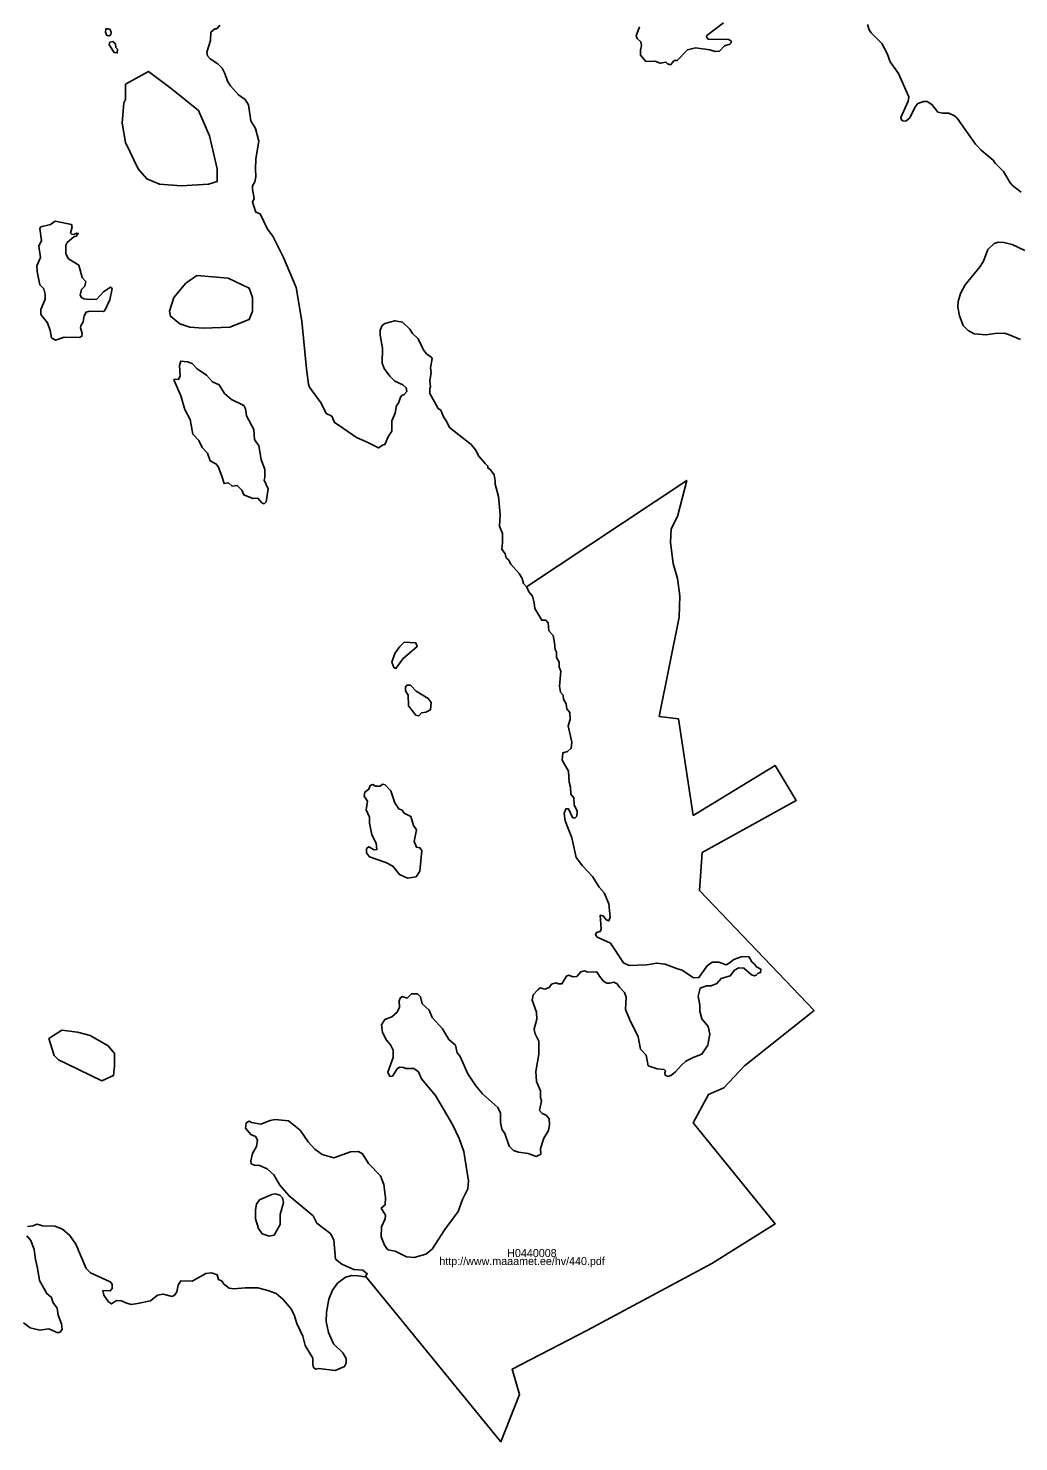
# Model space of a CAD drawing. Extents: x 369010 to 739155, y 6377141 to 6634081.
# Drawn here: x 378617 to 381710, y 6464683 to 6469097 of the extents above; entities that cross this region are included whole.
import ezdxf

# ---------------------------------------------------------------- set-up
doc = ezdxf.new("R2010")
doc.units = 0
for name, color, linetype in [('H_LINK', 7, 'Continuous'), ('H_PIIR', 7, 'Continuous'), ('H_TUNNUS', 7, 'Continuous')]:
    doc.layers.add(name, color=color, linetype=linetype)

msp = doc.modelspace()

# ---------------------------------------------------------------- linework, layer by layer
at = {"layer": 'H_PIIR'}
for points in [[(380525.63, 6469101.3447), (380515.3699, 6469073.5447), (380519.01, 6469065.6047), (380529.9301, 6469055.0147), (380531.92, 6469043.1047), (380528.94, 6469028.5447), (380529.2701, 6469013.3146), (380545.81, 6468993.4647), (380573.28, 6468994.4547), (380590.4901, 6468988.1647), (380608.3601, 6468991.4746), (380613.32, 6468986.5147), (380622.5899, 6468983.5347), (380634.1699, 6468996.1146), (380643.4299, 6468997.1046), (380675.1999, 6469029.5346), (380701.01, 6469035.8246), (380745.36, 6469029.5346), (380762.56, 6469024.9046), (380775.1401, 6469026.2247), (380791.02, 6469042.4347), (380808.23, 6469047.7347), (380811.8699, 6469051.7047), (380811.8699, 6469057.3247), (380804.9199, 6469061.9647), (380740.72, 6469062.9546), (380735.43, 6469070.8946), (380735.7599, 6469074.5346), (380788.04, 6469114.5747)], [(381237.7499, 6469109.2847), (381243.0501, 6469092.0747), (381248.6799, 6469083.4747), (381282.7599, 6469050.0447), (381299.3, 6469018.6146), (381308.2401, 6468992.8047), (381334.0499, 6468956.4047), (381366.4801, 6468883.6046), (381364.49, 6468869.7046), (381341.99, 6468818.0747), (381343.9801, 6468811.1247), (381347.9499, 6468808.4846), (381357.2201, 6468807.1546), (381369.46, 6468817.7446), (381386.6701, 6468851.8346), (381395.2699, 6468862.7546), (381412.4799, 6468868.3746), (381424.39, 6468868.0446), (381438.95, 6468859.4447), (381457.81, 6468834.9546), (381473.36, 6468832.3047), (381491.24, 6468832.6346), (381509.1, 6468823.7047), (381517.7101, 6468816.0946), (381574.6199, 6468735.3547), (381592.82, 6468716.8246), (381629.89, 6468685.0546), (381636.5101, 6468675.7846), (381662.3199, 6468650.3046), (381683.1599, 6468614.8947), (381690.44, 6468606.2947), (381717.9101, 6468585.1146)], [(378614.47, 6465354.6846), (378631.1, 6465357.0646), (378645.3599, 6465362.2946), (378661.99, 6465357.0646), (378700.01, 6465355.6447), (378724.25, 6465346.6046), (378747.0601, 6465326.6447), (378765.6, 6465299.5547), (378797.91, 6465223.5047), (378811.69, 6465210.1947), (378873, 6465182.1546), (378879.1801, 6465174.5546), (378879.1801, 6465161.7147), (378873.47, 6465153.6347), (378850.1899, 6465155.0646), (378853.51, 6465140.3247), (378867.3, 6465119.4147), (378876.8001, 6465113.2347), (378892.48, 6465124.1647), (378908.16, 6465123.2146), (378921.47, 6465116.0847), (378939.0499, 6465111.8146), (378958.0599, 6465114.1946), (378999.4, 6465122.7546), (379021.26, 6465140.8147), (379038.3701, 6465143.6647), (379066.89, 6465136.5346), (379074.97, 6465141.2846), (379081.6201, 6465150.7947), (379084.9499, 6465172.1846), (379093.5, 6465185.4946), (379129.14, 6465184.5446), (379171.91, 6465208.3047), (379189.0201, 6465210.6847), (379206.61, 6465204.0346), (379210.8801, 6465189.7746), (379222.2899, 6465184.5446), (379225.62, 6465177.4146), (379244.15, 6465162.2047), (379258.88, 6465160.7746), (379294.5201, 6465163.6246), (379334.2099, 6465163.6346), (379365.5701, 6465155.5546), (379391.23, 6465145.5747), (379413.09, 6465126.5647), (379436.86, 6465098.5146), (379447.3099, 6465079.5046), (379456.34, 6465051.9347), (379474.3999, 6465012.9646), (379482.24, 6464983.4947), (379505.52, 6464944.0447), (379505.52, 6464924.0846), (379507.4201, 6464914.5746), (379515.5001, 6464909.3446), (379525.01, 6464911.2547), (379575.86, 6464905.5447), (379604.8499, 6464917.9046), (379610.0699, 6464928.3646), (379610.31, 6464943.0947), (379599.86, 6464960.6746), (379570.3901, 6464988.7246), (379554.7099, 6465023.4146), (379547.1099, 6465058.5946), (379548.2999, 6465087.5846), (379555.9001, 6465128.4646), (379566.8299, 6465156.5047), (379582.9901, 6465178.3747), (379607.6999, 6465196.9047), (379627.66, 6465202.1347), (379647.1501, 6465201.1846), (379668.06, 6465197.8546), (379670.0236, 6465200.3116), (380092.86, 6464682.77), (380151.61, 6464830.17), (380128.11, 6464909.2199), (380363.1101, 6465030.9899), (380751.73, 6465239.08), (380949.3601, 6465363.18), (380693.51, 6465679.2), (380741.15, 6465766.9), (380788.7899, 6465788.41), (380854.0801, 6465856.2501), (381071.1101, 6466029.98), (380712.92, 6466403.93), (380721.74, 6466523.0599), (381014.65, 6466685.2199), (380949.3601, 6466794.4201), (380693.51, 6466638.87), (380647.6301, 6466940.03), (380587.64, 6466948.2999), (380649.39, 6467257.7201), (380651.91, 6467324.6501), (380644.1601, 6467378.95), (380630.59, 6467425.4999), (380622.84, 6467491.4301), (380624.77, 6467534.1001), (380644.1601, 6467572.89), (380673.24, 6467685.37), (380172.6387, 6467352.8072), (380163.9299, 6467363.3247), (380159.18, 6467378.5347), (380149.92, 6467394.6947), (380123.78, 6467423.6946), (380117.13, 6467436.9946), (380109.05, 6467443.6547), (380106.1999, 6467456.0146), (380095.74, 6467470.7447), (380098.1199, 6467491.1846), (380098.1199, 6467519.2247), (380088.85, 6467542.0446), (380090.28, 6467579.1147), (380085.9999, 6467635.2047), (380075.58, 6467673.3347), (380075.58, 6467684.0346), (380071.94, 6467702.9046), (380060.6899, 6467717.7947), (380052.42, 6467724.0747), (380052.42, 6467729.7047), (380043.4901, 6467737.6446), (380024.2899, 6467761.1446), (380013.3699, 6467780.3346), (380000.1399, 6467797.2047), (379932.3, 6467850.1546), (379924.69, 6467868.3547), (379914.0999, 6467883.5746), (379905.16, 6467904.0947), (379896.8901, 6467909.7247), (379870.75, 6467956.3746), (379871.08, 6467973.5846), (379873.4, 6467977.2247), (379871.4099, 6467997.4147), (379875.71, 6468021.2347), (379872.7401, 6468037.1246), (379878.03, 6468065.5847), (379875.38, 6468070.5446), (379860.82, 6468080.8046), (379849.9, 6468093.7046), (379846.5899, 6468104.6246), (379834.0201, 6468128.4547), (379817.47, 6468144.0047), (379808.21, 6468157.9047), (379785.7, 6468179.0846), (379761.8801, 6468183.7146), (379730.1099, 6468175.4446), (379722.4999, 6468169.4847), (379715.88, 6468154.2646), (379716.2099, 6468138.3847), (379723.1599, 6468098.6746), (379722.17, 6468051.0246), (379728.13, 6468035.1347), (379746.66, 6468010.3147), (379761.8801, 6467994.7646), (379787.03, 6467983.1847), (379797.6199, 6467974.5846), (379799.6, 6467962.9947), (379790.6699, 6467953.0647), (379784.05, 6467950.0947), (379779.0899, 6467944.7946), (379772.7999, 6467926.5947), (379767.17, 6467918.6546), (379762.87, 6467894.8247), (379752.28, 6467871.0046), (379752.6099, 6467839.2346), (379742.02, 6467823.3547), (379730.7701, 6467797.2047), (379725.4799, 6467796.5446), (379710.649, 6467786.5234), (379675.1795, 6467804.5045), (379642.0896, 6467819.0645), (379587.9301, 6467856.74), (379573.0401, 6467866.34), (379565.1, 6467886.19), (379547.89, 6467893.8001), (379531.3401, 6467926.56), (379495.2701, 6467975.8701), (379491.9702, 6467986.1301), (379486.3401, 6468033.78), (379471.2006, 6468182.0763), (379454.0026, 6468287.9099), (379414.3151, 6468381.8371), (379381.2421, 6468447.9831), (379363.8021, 6468470.3077), (379341.3021, 6468517.9578), (379327.4021, 6468522.9177), (379317.802, 6468554.3578), (379322.7721, 6468565.6077), (379317.1421, 6468594.0678), (379317.4721, 6468604.6578), (379324.752, 6468617.8878), (379328.0621, 6468633.7777), (379326.7421, 6468657.5978), (379328.0621, 6468689.3678), (379336.99, 6468744.6147), (379326.7299, 6468784.3246), (379312.5001, 6468808.1547), (379304.8901, 6468858.4547), (379294.9599, 6468874.3346), (379274.11, 6468888.8947), (379248.2999, 6468917.3547), (379239.37, 6468932.5746), (379231.42, 6468956.4047), (379223.15, 6468972.2846), (379209.5799, 6468985.8547), (379185.4299, 6469001.4047), (379176.8201, 6469011.3347), (379174.5101, 6469022.5846), (379186.75, 6469058.9846), (379187.7399, 6469085.4546), (379199.3301, 6469095.0547), (379205.6099, 6469095.3846), (379215.5401, 6469106.6346)], [(381728.5, 6468402.7846), (381689.12, 6468422.3047), (381663.31, 6468428.5947), (381646.1, 6468428.9246), (381633.2, 6468424.9547), (381614.0001, 6468406.0947), (381599.77, 6468370.0246), (381589.85, 6468352.8147), (381542.2, 6468296.2246), (381527.9699, 6468269.4246), (381520.69, 6468243.6146), (381519.3601, 6468226.4046), (381524.9899, 6468199.2746), (381536.24, 6468169.1546), (381552.1199, 6468153.2747), (381571.3201, 6468142.6846), (381608.38, 6468139.7046), (381634.8501, 6468144.0047), (381663.97, 6468144.6647), (381678.5299, 6468140.6947), (381715.5901, 6468125.4746)], [(378602.1099, 6465053.8247), (378623.4901, 6465038.6146), (378652.9601, 6465031.4846), (378681.47, 6465035.7547), (378709.9899, 6465022.9246), (378718.0699, 6465026.2546), (378723.2901, 6465034.3346), (378720.9199, 6465050.9647), (378710.94, 6465077.5846), (378707.1401, 6465100.4047), (378693.8299, 6465118.9347), (378689.55, 6465133.6746), (378675.2999, 6465145.5547), (378652.48, 6465185.9547), (378646.31, 6465224.9346), (378640.1299, 6465252.0246), (378635.85, 6465282.9147), (378624.92, 6465310.9646), (378613.0399, 6465326.1747)]]:
    msp.add_lwpolyline(points, dxfattribs=at)
for points in [[(378867.1283, 6469095.6707), (378872.7554, 6469093.0227), (378876.2309, 6469083.7544), (378875.238, 6469077.6307), (378869.6108, 6469073.1622), (378862.3287, 6469074.9827), (378858.6876, 6469085.4094), (378859.8462, 6469095.0086)], [(378895.4295, 6469031.9516), (378894.9329, 6469020.5319), (378885.3337, 6469021.8558), (378869.4454, 6469045.0265), (378872.0934, 6469053.6327), (378881.5271, 6469055.6187), (378889.1404, 6469048.1711), (378890.6299, 6469037.4133)], [(378920.8662, 6468922.9111), (378992.3038, 6468962.5987), (379063.7414, 6468909.6819), (379148.4083, 6468840.8901), (379182.8042, 6468761.515), (379206.6167, 6468658.3273), (379206.6167, 6468618.6397), (379180.1583, 6468610.7022), (379095.4915, 6468605.4105), (379026.6997, 6468610.7022), (378987.0121, 6468626.5772), (378960.5537, 6468658.3273), (378920.8662, 6468740.3483), (378910.2828, 6468801.2026), (378915.5745, 6468864.7027), (378920.8662, 6468875.286)], [(378644.691, 6468337.6624), (378644.0289, 6468354.8748), (378654.9522, 6468381.8519), (378650.3181, 6468416.6077), (378658.2623, 6468434.8133), (378653.6281, 6468471.8862), (378656.6073, 6468477.1822), (378686.7289, 6468484.1334), (378700.9623, 6468495.0567), (378751.9376, 6468484.7955), (378754.5856, 6468477.5133), (378749.2894, 6468457.3218), (378752.5996, 6468454.0117), (378759.8817, 6468453.6806), (378767.4948, 6468457.3218), (378773.1221, 6468456.3288), (378766.8329, 6468447.7226), (378759.2197, 6468446.0675), (378738.6972, 6468428.1931), (378734.0631, 6468420.2489), (378734.394, 6468392.4443), (378743.0002, 6468377.0523), (378774.7771, 6468357.1919), (378785.3693, 6468318.464), (378796.9546, 6468305.8856), (378793.9755, 6468291.9832), (378783.7143, 6468281.06), (378779.4112, 6468263.5166), (378783.7143, 6468255.9033), (378790.9964, 6468251.9313), (378807.5468, 6468250.2762), (378831.3795, 6468251.6003), (378852.5639, 6468273.7778), (378873.7484, 6468289.0043), (378879.0446, 6468285.032), (378872.4245, 6468248.9523), (378856.205, 6468215.5204), (378852.5639, 6468213.2033), (378808.8709, 6468213.5344), (378797.6167, 6468210.8863), (378791.3275, 6468199.3011), (378789.0104, 6468180.4337), (378781.7283, 6468167.5242), (378780.7352, 6468161.5662), (378786.0313, 6468143.6917), (378784.7072, 6468135.4166), (378776.7631, 6468131.1134), (378729.4289, 6468132.1064), (378702.6173, 6468122.8383), (378689.7081, 6468130.7825), (378685.736, 6468152.96), (378677.1297, 6468176.7925), (378656.2761, 6468202.9421), (378656.9382, 6468219.1616), (378669.8476, 6468250.9383), (378670.1785, 6468266.8266), (378665.8755, 6468283.377), (378652.9661, 6468296.2864)], [(379108.7207, 6468301.1391), (379143.1166, 6468324.9516), (379241.0126, 6468317.0141), (379307.1586, 6468285.264), (379317.742, 6468256.1598), (379317.742, 6468213.8264), (379307.1586, 6468187.368), (379246.3043, 6468163.5554), (379164.2833, 6468160.9096), (379121.9499, 6468163.5554), (379090.1998, 6468174.1388), (379061.0956, 6468197.9513), (379058.4498, 6468213.8264), (379071.679, 6468256.1598)], [(379222.1343, 6467698.6514), (379210.5491, 6467729.1042), (379202.9359, 6467737.3793), (379185.0614, 6467745.9855), (379176.4552, 6467770.4801), (379160.5668, 6467787.6926), (379149.9747, 6467809.3737), (379131.4381, 6467829.565), (379123.163, 6467874.9132), (379105.6196, 6467906.6899), (379093.7032, 6467949.059), (379072.8498, 6467996.7242), (379073.1807, 6468001.6893), (379086.0901, 6468000.6963), (379091.3863, 6468011.9505), (379089.0692, 6468043.7273), (379093.7032, 6468057.6297), (379114.5568, 6468055.9746), (379129.1211, 6468050.3475), (379144.6785, 6468034.1281), (379174.1383, 6468013.6056), (379192.6747, 6467993.0831), (379212.8662, 6467984.1459), (379230.4096, 6467957.0032), (379251.925, 6467937.8048), (379290.322, 6467919.5994), (379295.2871, 6467908.6761), (379298.9282, 6467886.8295), (379321.7678, 6467844.4604), (379323.7538, 6467812.6837), (379336.6632, 6467792.8233), (379344.6074, 6467750.6197), (379355.8616, 6467718.843), (379356.1927, 6467694.0173), (379353.71, 6467685.9076), (379366.7849, 6467659.2615), (379360.4957, 6467618.3819), (379354.2066, 6467612.0928), (379346.759, 6467614.741), (379334.3461, 6467629.4709), (379318.1266, 6467628.8088), (379289.8254, 6467639.8976), (379284.5294, 6467655.1239), (379269.303, 6467669.6883), (379253.7457, 6467667.0402), (379242.1604, 6467677.6325), (379228.5891, 6467675.9775)], [(380172.6387, 6467352.8072), (380673.24, 6467685.37), (380644.1601, 6467572.89), (380624.77, 6467534.1001), (380622.84, 6467491.4301), (380630.59, 6467425.4999), (380644.1601, 6467378.95), (380651.91, 6467324.6501), (380649.39, 6467257.7201), (380587.64, 6466948.2999), (380647.6301, 6466940.03), (380693.51, 6466638.87), (380949.3601, 6466794.4201), (381014.65, 6466685.2199), (380721.74, 6466523.0599), (380712.92, 6466403.93), (381071.1101, 6466029.98), (380854.0801, 6465856.2501), (380788.7899, 6465788.41), (380741.15, 6465766.9), (380693.51, 6465679.2), (380949.3601, 6465363.18), (380751.73, 6465239.08), (380363.1101, 6465030.9899), (380128.11, 6464909.2199), (380151.61, 6464830.17), (380092.86, 6464682.77), (379670.0236, 6465200.3116), (379675.66, 6465207.3647), (379661.88, 6465218.2947), (379633.8401, 6465220.1946), (379596.53, 6465236.8346), (379577.05, 6465252.9946), (379570.8701, 6465311.9346), (379561.84, 6465331.8947), (379518.12, 6465365.6446), (379506.95, 6465387.9746), (379431.8701, 6465450.2447), (379402.4001, 6465484.4646), (379383.8699, 6465516.7846), (379362.95, 6465534.8346), (379339.67, 6465545.2947), (379323.9801, 6465546.2446), (379313.5299, 6465550.5247), (379311.8601, 6465560.0246), (379317.5699, 6465583.3147), (379329.45, 6465605.1746), (379332.77, 6465624.6646), (379326.6, 6465635.5946), (379311.8601, 6465642.7246), (379295.7101, 6465661.7346), (379297.61, 6465678.3746), (379306.6401, 6465683.6046), (379314.24, 6465679.3247), (379343.23, 6465674.5747), (379372.69, 6465685.9846), (379388.6201, 6465688.8346), (379429.96, 6465685.0347), (379466.5501, 6465655.5647), (379490.7901, 6465618.9646), (379511.7, 6465596.1547), (379535.22, 6465579.5147), (379571.3399, 6465569.0547), (379623.14, 6465588.5447), (379648.32, 6465589.0246), (379661.16, 6465581.4146), (379679.9201, 6465551.9446), (379717.4701, 6465512.9747), (379726.97, 6465485.8747), (379733.15, 6465445.4747), (379731.2499, 6465423.1347), (379719.6099, 6465412.6847), (379732.4401, 6465390.8247), (379731.97, 6465378.4646), (379720.56, 6465353.7447), (379719.1299, 6465322.3746), (379730.0599, 6465296.2346), (379740.0401, 6465282.4546), (379763.0901, 6465277.6947), (379798.2601, 6465260.5846), (379822.4901, 6465257.7346), (379858.61, 6465268.6646), (379878.09, 6465284.3446), (379918.2501, 6465345.1847), (379960.07, 6465402.2247), (379972.9, 6465439.7747), (379989.7701, 6465472.5647), (379992.1401, 6465497.7646), (379976.94, 6465589.0146), (379962.2, 6465629.8946), (379941.53, 6465673.1446), (379888.3101, 6465764.4046), (379845.3, 6465816.2046), (379835.7901, 6465837.5946), (379821.06, 6465848.5246), (379796.3499, 6465848.0546), (379788.75, 6465851.3846), (379776.8701, 6465852.3347), (379768.7901, 6465847.5747), (379754.53, 6465824.7646), (379746.45, 6465823.8146), (379739.8, 6465837.1246), (379757.1399, 6465883.2246), (379756.1901, 6465906.0447), (379748.1101, 6465922.6747), (379735.76, 6465936.4647), (379722.93, 6465960.7047), (379720.55, 6465984.9447), (379730.53, 6466001.5746), (379752.6301, 6466009.6546), (379768.7901, 6466024.3946), (379776.8701, 6466040.0746), (379775.44, 6466059.5647), (379778.77, 6466068.1247), (379784.9501, 6466073.3447), (379800.63, 6466068.5947), (379813.93, 6466081.4247), (379832.47, 6466081.9047), (379842.45, 6466072.3946), (379847.1999, 6466050.0546), (379869.0599, 6466030.5747), (379878.8, 6466007.7546), (379911.12, 6465972.5846), (379930.13, 6465939.3147), (379951.51, 6465921.2546), (379956.2599, 6465897.0146), (379965.77, 6465885.6046), (379990.01, 6465831.8946), (380014.72, 6465794.3446), (380035.63, 6465769.6246), (380083.62, 6465726.8546), (380092.18, 6465709.2647), (380092.18, 6465680.2747), (380096.4499, 6465659.3546), (380105.01, 6465645.5746), (380119.27, 6465606.1246), (380132.1, 6465591.8646), (380147.7799, 6465586.6346), (380178.19, 6465583.3147), (380202.91, 6465573.3246), (380217.6399, 6465580.4547), (380217.1601, 6465598.9947), (380227.14, 6465631.3147), (380241.4001, 6465654.6046), (380244.7299, 6465673.1446), (380243.29, 6465690.7347), (380234.74, 6465702.6146), (380222.3801, 6465708.3246), (380213.35, 6465717.3547), (380219.53, 6465747.7747), (380216.68, 6465758.2247), (380217.1501, 6465778.1946), (380204.3199, 6465807.6646), (380202.42, 6465839.0347), (380211.45, 6465892.7347), (380211.45, 6465934.0946), (380199.0899, 6465958.3346), (380197.19, 6465972.5946), (380204.8, 6466002.0646), (380203.8501, 6466024.8847), (380191.0099, 6466061.4846), (380193.3899, 6466078.1146), (380208.12, 6466094.2746), (380215.73, 6466099.9746), (380230.4601, 6466096.1746), (380244.2401, 6466101.4046), (380251.37, 6466111.3847), (380264.68, 6466115.6646), (380273.23, 6466112.8146), (380283.68, 6466113.2846), (380297.47, 6466136.5746), (380305.54, 6466140.3846), (380317.9, 6466135.1546), (380329.78, 6466135.6247), (380342.14, 6466150.8346), (380354.02, 6466153.2146), (380364.95, 6466149.4147), (380392.5101, 6466150.3646), (380400.5901, 6466136.5746), (380413.9001, 6466121.3746), (380423.4, 6466115.1946), (380433.3799, 6466115.1946), (380445.74, 6466117.5746), (380455.72, 6466112.8146), (380462.8499, 6466102.3646), (380478.5301, 6466085.7246), (380483.7601, 6466071.4647), (380481.8599, 6466032.4946), (380494.6901, 6466002.0746), (380521.7801, 6465946.9347), (380529.38, 6465908.4346), (380546.96, 6465890.3747), (380553.14, 6465857.1046), (380580.71, 6465847.1247), (380602.5701, 6465845.6946), (380607.32, 6465840.9446), (380604.9401, 6465834.7646), (380606.37, 6465827.1546), (380613.9699, 6465823.8346), (380623.48, 6465826.6846), (380638.69, 6465837.6146), (380656.2701, 6465858.0547), (380671, 6465870.8847), (380693.81, 6465882.7647), (380720.9001, 6465893.2247), (380738.96, 6465920.7946), (380745.6101, 6465955.4947), (380739.9101, 6465979.7347), (380720.9001, 6466003.9747), (380714.25, 6466027.2646), (380714.72, 6466046.2747), (380709.02, 6466073.8447), (380715.19, 6466099.0346), (380735.1499, 6466107.1146), (380749.41, 6466106.6347), (380767.4699, 6466114.2447), (380780.3001, 6466129.9247), (380809.29, 6466137.5346), (380822.59, 6466156.0646), (380836.38, 6466163.1947), (380851.1099, 6466162.2447), (380875.3499, 6466141.3347), (380884.85, 6466138.0047), (380890.55, 6466140.3846), (380896.2601, 6466146.0847), (380903.86, 6466147.9846), (380904.3301, 6466158.4446), (380891.0301, 6466165.5747), (380884.85, 6466174.1347), (380876.3, 6466181.2547), (380866.7901, 6466197.8947), (380843.5, 6466197.4247), (380820.22, 6466188.3846), (380805.4899, 6466176.9846), (380796.22, 6466172.2246), (380773.8801, 6466180.3046), (380752.97, 6466180.3046), (380736.81, 6466169.3746), (380711.15, 6466132.3046), (380694.04, 6466131.3546), (380659.35, 6466155.1147), (380641.2901, 6466160.8146), (380605.65, 6466174.1246), (380578.7999, 6466177.9246), (380548.3901, 6466172.2246), (380493.26, 6466169.8446), (380475.92, 6466178.4047), (380435.05, 6466240.1946), (380393.7001, 6466258.2546), (380388.4701, 6466266.3346), (380391.7999, 6466273.4647), (380403.21, 6466275.8347), (380406.53, 6466283.9147), (380403.4499, 6466327.1647), (380413.43, 6466324.3147), (380421.9801, 6466312.9146), (380429.59, 6466309.5846), (380433.86, 6466320.9946), (380429.59, 6466362.8147), (380415.33, 6466397.0347), (380400.12, 6466415.1046), (380378.7401, 6466447.8946), (380347.3699, 6466481.1647), (380327.65, 6466507.7847), (380314.82, 6466568.6246), (380293.44, 6466622.3346), (380290.11, 6466644.6746), (380295.34, 6466659.4047), (380304.37, 6466659.4047), (380316.72, 6466632.3147), (380323.38, 6466629.9346), (380329.79, 6466636.5946), (380331.2099, 6466652.7546), (380321.71, 6466670.8146), (380320.76, 6466694.1047), (380311.2501, 6466705.0347), (380310.78, 6466726.8947), (380306.0301, 6466743.0547), (380304.36, 6466776.8046), (380284.41, 6466811.0246), (380286.3099, 6466833.8447), (380301.04, 6466838.1246), (380312.44, 6466848.5746), (380314.34, 6466867.5946), (380303.18, 6466918.9246), (380308.8801, 6466938.8847), (380308.41, 6466960.2746), (380299.38, 6466972.1547), (380297, 6466986.8846), (380288.45, 6467001.6247), (380287.0201, 6467013.9846), (380279.4201, 6467023.9646), (380275.62, 6467042.5047), (380280.13, 6467089.5546), (380274.9001, 6467101.4447), (380274.9001, 6467117.1247), (380266.35, 6467132.3346), (380266.35, 6467148.9746), (380262.0699, 6467157.5247), (380260.64, 6467177.9646), (380256.3701, 6467200.3046), (380242.82, 6467215.5146), (380240.92, 6467240.2246), (380233.7899, 6467248.3046), (380220.4799, 6467248.3046), (380198.6199, 6467284.9047), (380197.2, 6467302.9646), (380191.97, 6467323.8746), (380180.0899, 6467337.1846), (380175.34, 6467349.5447)], [(379791.3027, 6467179.9619), (379827.879, 6467177.6449), (379831.189, 6467166.2252), (379786.9995, 6467127.8282), (379765.1531, 6467097.872), (379759.0294, 6467100.6856), (379752.7402, 6467117.7324), (379761.3464, 6467144.3786), (379777.0693, 6467166.2252)], [(379837.1472, 6466949.9114), (379827.2169, 6466951.8975), (379804.874, 6466981.3571), (379803.881, 6467014.6234), (379795.2748, 6467027.8638), (379794.9436, 6467038.9525), (379799.5778, 6467045.5728), (379810.9976, 6467045.5728), (379828.541, 6467027.0362), (379865.6139, 6467003.7001), (379875.7097, 6466991.7838), (379873.2271, 6466968.9443), (379858.4972, 6466961.0001), (379845.2569, 6466959.0142)], [(379801.5639, 6466443.3036), (379776.4073, 6466454.7235), (379755.8848, 6466480.3765), (379734.0382, 6466491.7964), (379682.4011, 6466509.3397), (379672.9673, 6466521.7526), (379672.9673, 6466535.4893), (379680.5804, 6466540.7855), (379697.1308, 6466531.1863), (379705.737, 6466532.6759), (379703.9165, 6466551.7088), (379690.0141, 6466577.8584), (379682.8975, 6466614.4347), (379682.4011, 6466633.4678), (379671.8087, 6466656.3074), (379676.6083, 6466682.9534), (379666.0161, 6466699.5038), (379668.0021, 6466711.9166), (379680.7459, 6466720.3574), (379685.0491, 6466732.2736), (379693.3242, 6466735.2527), (379701.9304, 6466730.4531), (379715.6673, 6466730.4531), (379723.777, 6466736.0803), (379731.3902, 6466734.2598), (379749.4302, 6466715.7232), (379761.3464, 6466677.6574), (379774.2557, 6466659.1208), (379784.6824, 6466654.8178), (379790.8061, 6466645.8805), (379812.1561, 6466635.2883), (379820.2657, 6466607.8146), (379829.3685, 6466593.5813), (379821.7553, 6466557.005), (379829.3685, 6466539.296), (379840.2918, 6466537.9719), (379845.7535, 6466529.3658), (379839.4643, 6466465.1502), (379828.2101, 6466446.6136)], [(378738.1328, 6465862.5564), (378711.6744, 6465875.7856), (378698.4452, 6465889.0148), (378681.9087, 6465941.9315), (378721.5963, 6465968.3899), (378771.2058, 6465961.7753), (378810.8934, 6465951.8534), (378867.1175, 6465918.7804), (378886.9612, 6465895.6294), (378886.9612, 6465855.9418), (378883.6539, 6465826.1761), (378847.2737, 6465809.6396)], [(379388.1349, 6465456.8999), (379402.8648, 6465453.0933), (379411.471, 6465444.4871), (379413.7881, 6465429.7572), (379404.0232, 6465392.6843), (379404.0232, 6465360.9076), (379385.4869, 6465328.1377), (379369.9294, 6465324.8277), (379347.9174, 6465332.2753), (379336.1666, 6465348.9913), (379327.064, 6465378.9475), (379326.5674, 6465406.9176), (379329.8774, 6465424.9576), (379338.9802, 6465438.3634), (379377.377, 6465455.4104)]]:
    msp.add_lwpolyline(points, close=True, dxfattribs=at)

# ---------------------------------------------------------------- texts
at = {"layer": 'H_LINK'}
msp.add_text('http://www.maaamet.ee/hv/440.pdf', height=25, rotation=360, dxfattribs=at).set_placement((379900.9363, 6465234.5399))
at = {"layer": 'H_TUNNUS'}
msp.add_text('H0440008', height=25, rotation=360, dxfattribs=at).set_placement((380112.7909, 6465259.5399))

doc.saveas('drawing.dxf')
